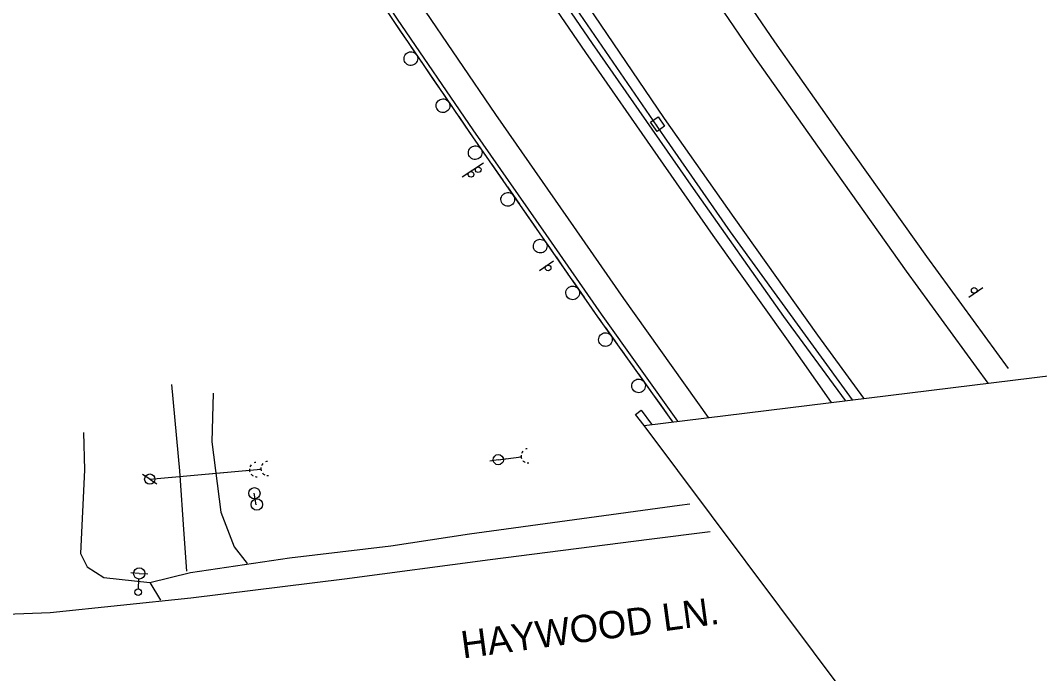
# Model space of a CAD drawing. Extents: x 1746719 to 1766531, y 631721 to 662391.
# Drawn here: x 1764475.4 to 1764923.1, y 632583.4 to 632870.3 of the extents above; entities that cross this region are included whole.
import ezdxf

# ---------------------------------------------------------------- set-up
doc = ezdxf.new("R2010")
doc.units = 0
for name, color, linetype in [('SURVEY - AERIAL SURVEY - Photo Control - Points - Elevations', 7, 'Continuous'), ('SURVEY - AERIAL SURVEY - Photo Control - Points - Numbers', 7, 'Continuous'), ('SURVEY - CENTERLINE - Existing Roads - Development', 7, 'Continuous'), ('SURVEY - CENTERLINE - Existing Roads Text', 7, 'Continuous'), ('SURVEY - CENTERLINE - Preliminary Curve Text', 7, 'Continuous'), ('SURVEY - CONTROL - Grid', 7, 'Continuous'), ('SURVEY - CONTROL - Points - Numbers', 7, 'Continuous')]:
    doc.layers.add(name, color=color, linetype=linetype)

msp = doc.modelspace()

# ---------------------------------------------------------------- linework, layer by layer
at = {"layer": 'SURVEY - AERIAL SURVEY - Photo Control - Points - Elevations'}
for points in [[(1764286.91, 633632.22), (1764324.36, 633555.72), (1764364.46, 633475.61), (1764397.7, 633413.21), (1764435.38, 633344.82), (1764469.06, 633284.69), (1764504.2, 633224.1), (1764542.48, 633159.48), (1764578.77, 633099.35), (1764616.47, 633039.95), (1764651.83, 632984.84), (1764692.24, 632923.64), (1764727.21, 632872.71), (1764758.15, 632827.22), (1764788.79, 632783.76), (1764825.53, 632732.1), (1764845.75, 632704.38)], [(1764831.69, 632702.44), (1764811.98, 632730.49), (1764779.64, 632775.81), (1764755.56, 632810.46), (1764723.74, 632856.23), (1764690.96, 632904.23), (1764661.37, 632949.17), (1764640.02, 632981.61), (1764615.9, 633018.34), (1764577.35, 633078.68), (1764534.79, 633147.94), (1764491.74, 633220.52), (1764453.8, 633286.81), (1764418.29, 633350.37), (1764381.37, 633418.77), (1764346.73, 633485.01), (1764310.57, 633557.37), (1764276.55, 633626.71)], [(1764777.7, 632695.9), (1764740.39, 632748.17), (1764716.15, 632783.07), (1764684.21, 632828.99), (1764651.09, 632877.5), (1764621.28, 632922.78), (1764599.91, 632955.24), (1764575.61, 632992.25), (1764536.68, 633053.19), (1764493.7, 633123.13), (1764450.26, 633196.35), (1764412.02, 633263.19), (1764376.22, 633327.26), (1764338.98, 633396.24), (1764291.02, 633487.95)], [(1764503.63, 633321.19), (1764510.76, 633308.46), (1764545.61, 633248.38), (1764583.68, 633184.11), (1764619.58, 633124.62), (1764656.94, 633065.77), (1764692.06, 633011.03), (1764732.06, 632950.46), (1764766.84, 632899.8), (1764797.62, 632854.55), (1764827.96, 632811.5), (1764864.47, 632760.16), (1764900.35, 632710.98)], [(1764562.65, 633241.21), (1764593.12, 633189.76), (1764628.94, 633130.41), (1764666.21, 633071.69), (1764701.28, 633017.03), (1764741.18, 632956.6), (1764775.93, 632906), (1764806.66, 632860.81), (1764836.94, 632817.85), (1764873.4, 632766.58), (1764909.24, 632717.46)], [(1764764.15, 632694.23), (1764730.58, 632741.26), (1764706.3, 632776.22), (1764674.33, 632822.18), (1764641.12, 632870.82), (1764611.26, 632916.18), (1764589.88, 632948.65), (1764565.54, 632985.72), (1764526.51, 633046.82), (1764518.3, 633060.18)], [(1764548.59, 632628.46), (1764547.4, 632644.66), (1764545.39, 632672.52), (1764541.98, 632710.4)], [(1764560.1, 632706.53), (1764559.52, 632685.19), (1764563.44, 632654.29), (1764569.34, 632639.14), (1764574.99, 632631.74)], [(1764503.09, 632689.36), (1764503.52, 632672.91), (1764501.82, 632636.21), (1764504.69, 632630.36), (1764512, 632625.61), (1764532.24, 632623.4), (1764536.91, 632615.65)], [(1764532.24, 632623.4), (1764550.11, 632627.79), (1764593.57, 632634.3), (1764638.12, 632639.6), (1764672.65, 632644.86), (1764764.86, 632657.4), (1764769.51, 632657.94)], [(1764414.91, 632607.55), (1764488.46, 632610.23), (1764550.26, 632616.68), (1764617.8, 632625.11), (1764681.69, 632633.6), (1764751.52, 632642.43), (1764778.33, 632645.89)]]:
    msp.add_lwpolyline(points, dxfattribs=at)
at = {"layer": 'SURVEY - AERIAL SURVEY - Photo Control - Points - Numbers'}
for points in [[(1764283.41, 633629.46), (1764296.35, 633602.51), (1764334.35, 633526.38), (1764369.12, 633457.05), (1764408.67, 633383.28), (1764437.22, 633331.71), (1764463.82, 633284.24), (1764490.85, 633237.46), (1764535.54, 633161.37), (1764569.37, 633106.49), (1764606.28, 633047.19), (1764645.68, 632986.22), (1764676.08, 632939.9), (1764709.83, 632889.53), (1764732.42, 632856.58), (1764758.21, 632819.17), (1764787.18, 632777.39), (1764806.45, 632750.71), (1764840.69, 632703.63)], [(1764837.81, 632703.35), (1764810.72, 632740.31), (1764770.99, 632796.4), (1764726.66, 632860.1), (1764677.61, 632931.8), (1764621.09, 633019), (1764574.03, 633093.64), (1764526.02, 633172.29), (1764474.29, 633260.27), (1764434.46, 633331.05), (1764406.76, 633381.58), (1764368.12, 633452.62), (1764325.13, 633538.21), (1764281.43, 633628.12)], [(1764614.81, 632907.15), (1764639.46, 632869.71), (1764672.68, 632821.05), (1764704.65, 632775.08), (1764728.95, 632740.11), (1764761.89, 632693.95)], [(1764639.73, 632869.31), (1764642.38, 632865.43)], [(1764642.38, 632865.43), (1764645.03, 632861.55)], [(1764646.83, 632858.91), (1764652.02, 632851.31)], [(1764653.82, 632848.67), (1764656.48, 632844.79)], [(1764656.48, 632844.79), (1764659.12, 632840.91)], [(1764660.93, 632838.26), (1764666.12, 632830.66)], [(1764667.92, 632828.02), (1764670.57, 632824.14)], [(1764670.57, 632824.14), (1764672.68, 632821.05), (1764673.23, 632820.26)], [(1764675.06, 632817.64), (1764680.31, 632810.08)], [(1764682.14, 632807.46), (1764684.82, 632803.6)], [(1764684.82, 632803.6), (1764687.5, 632799.74)], [(1764689.33, 632797.11), (1764694.58, 632789.56)], [(1764696.41, 632786.93), (1764699.09, 632783.07)], [(1764699.09, 632783.07), (1764701.78, 632779.21)], [(1764703.6, 632776.59), (1764704.66, 632775.08), (1764708.85, 632769.03)], [(1764710.68, 632766.4), (1764713.36, 632762.54)], [(1764713.36, 632762.54), (1764716.04, 632758.68)], [(1764717.87, 632756.06), (1764723.12, 632748.5)], [(1764724.94, 632745.87), (1764727.62, 632742.01)], [(1764727.62, 632742.01), (1764728.95, 632740.11), (1764730.33, 632738.17)], [(1764732.19, 632735.56), (1764737.53, 632728.08)], [(1764739.39, 632725.47), (1764742.12, 632721.65)], [(1764742.12, 632721.65), (1764744.85, 632717.82)], [(1764746.71, 632715.22), (1764752.06, 632707.73)], [(1764753.92, 632705.12), (1764756.65, 632701.3)], [(1764756.65, 632701.3), (1764759.38, 632697.47)], [(1764761.24, 632694.87), (1764761.89, 632693.95)]]:
    msp.add_lwpolyline(points, dxfattribs=at)
for centre, start, end in [((1764646.92, 632853.46), 147.5931, 147.5791), ((1764661.02, 632832.81), 147.5931, 147.5791), ((1764675.19, 632812.18), 148.0851, 148.0712), ((1764689.47, 632791.66), 148.0851, 148.0712), ((1764703.74, 632771.14), 148.0553, 148.0413), ((1764718, 632750.6), 148.0553, 148.0413), ((1764732.39, 632730.11), 148.7863, 148.7723), ((1764746.92, 632709.77), 148.7863, 148.7723)]:
    msp.add_arc(centre, 3, start, end, dxfattribs=at)
at = {"layer": 'SURVEY - CENTERLINE - Existing Roads - Development'}
for p, q in [((1764685.33, 632677.36), (1764681.63, 632676.78)), ((1764685.33, 632677.36), (1764695.38, 632678.64)), ((1764685.33, 632677.36), (1764689.04, 632677.94)), ((1764694.71, 632678.55), (1764695.38, 632678.64)), ((1764532.23, 632668.84), (1764529.07, 632670.87)), ((1764532.23, 632668.84), (1764581.08, 632673.21)), ((1764532.23, 632668.84), (1764576.04, 632672.72)), ((1764575.34, 632672.66), (1764576.04, 632672.72)), ((1764580.39, 632673.15), (1764581.08, 632673.21)), ((1764532.23, 632668.84), (1764535.38, 632666.82)), ((1764527.63, 632627.44), (1764523.89, 632627.66)), ((1764527.63, 632627.44), (1764531.37, 632627.22)), ((1764527.23, 632620.7), (1764527.48, 632624.94))]:
    msp.add_line(p, q, dxfattribs=at)
for centre, radius in [((1764685.33, 632677.36), 2.25), ((1764532.23, 632668.84), 2.25), ((1764527.63, 632627.44), 2.5), ((1764527.14, 632619.2), 1.5)]:
    msp.add_circle(centre, radius, dxfattribs=at)
for start, end in [(136.9354, 157.2779), (95.0575, 109.6784), (172.5784, 199.0937), (218.6202, 243.3903), (260.244, 274.1334)]:
    msp.add_arc((1764579.12, 632673.02), 3.12, start, end, dxfattribs=at)
for centre, major_axis, ratio, start_param, end_param in [((1764698.36, 632679.04), (-0.39, 3.1), 0.969713, 1.352995, 1.815775), ((1764698.36, 632679.04), (-0.39, 3.1), 0.969713, 0.730907, 1.085951), ((1764698.36, 632679.04), (-0.39, 3.1), 0.969713, 0, 0.255182), ((1764584.17, 632673.51), (-0.28, 3.11), 0.999988, 0.730907, 1.085951), ((1764584.17, 632673.51), (-0.28, 3.11), 0.999988, 0, 0.255182), ((1764698.36, 632679.04), (-0.39, 3.1), 0.969713, 2.156577, 2.588895), ((1764698.36, 632679.04), (-0.39, 3.1), 0.969713, 2.883049, 3.125465), ((1764584.17, 632673.51), (-0.28, 3.11), 0.999988, 1.352995, 1.815775), ((1764584.17, 632673.51), (-0.28, 3.11), 0.999988, 2.156577, 2.588895), ((1764584.17, 632673.51), (-0.28, 3.11), 0.999988, 2.883049, 3.125465)]:
    msp.add_ellipse(centre, major_axis=major_axis, ratio=ratio, start_param=start_param, end_param=end_param, dxfattribs=at)
at = {"layer": 'SURVEY - CENTERLINE - Existing Roads Text'}
for p, q in [((1764749.37, 632692.41), (1764929.23, 632714.53)), ((1764745.57, 632697.22), (1764748.04, 632699.13)), ((1764749.37, 632692.41), (1764745.57, 632697.22)), ((1764748.04, 632699.13), (1764752.58, 632692.96)), ((1764863.18, 632540.46), (1764749.37, 632692.41))]:
    msp.add_line(p, q, dxfattribs=at)
at = {"layer": 'SURVEY - CENTERLINE - Preliminary Curve Text'}
msp.add_line((1764755.31, 632824.71), (1764755.31, 632824.71), dxfattribs=at)
msp.add_lwpolyline([(1764752.24, 632825.62), (1764755.52, 632827.91), (1764758.38, 632823.8), (1764755.09, 632821.52), (1764752.24, 632825.62)], dxfattribs=at)
at = {"layer": 'SURVEY - CONTROL - Grid'}
for p, q in [((1764669.48, 632801.61), (1764678.87, 632807.7)), ((1764703.4, 632760.39), (1764709.54, 632764.7)), ((1764898.14, 632752.82), (1764891.95, 632748.59)), ((1764578.18, 632662.59), (1764578.18, 632662.59)), ((1764578.18, 632662.59), (1764578.18, 632662.59)), ((1764579.27, 632657.66), (1764579.27, 632657.66)), ((1764579.27, 632657.66), (1764579.27, 632657.66))]:
    msp.add_line(p, q, dxfattribs=at)
for points in [[(1764579.01, 632657.59), (1764578.05, 632662.61)], [(1764579.01, 632657.6), (1764578.05, 632662.62)]]:
    msp.add_lwpolyline(points, dxfattribs=at)
for centre, radius in [((1764676.5, 632804.7), 1.25), ((1764673.35, 632802.66), 1.25), ((1764707.19, 632761.55), 1.25), ((1764894.34, 632751.7), 1.25), ((1764578.18, 632662.61), 2.5), ((1764578.18, 632662.61), 2.5), ((1764579.27, 632657.68), 2.5), ((1764579.27, 632657.68), 2.5)]:
    msp.add_circle(centre, radius, dxfattribs=at)

# ---------------------------------------------------------------- texts
at = {"layer": 'SURVEY - CONTROL - Points - Numbers'}
msp.add_text('HAYWOOD LN.', height=12, rotation=7.7194, dxfattribs=at).set_placement((1764669.8, 632590.03))

doc.saveas('drawing.dxf')
